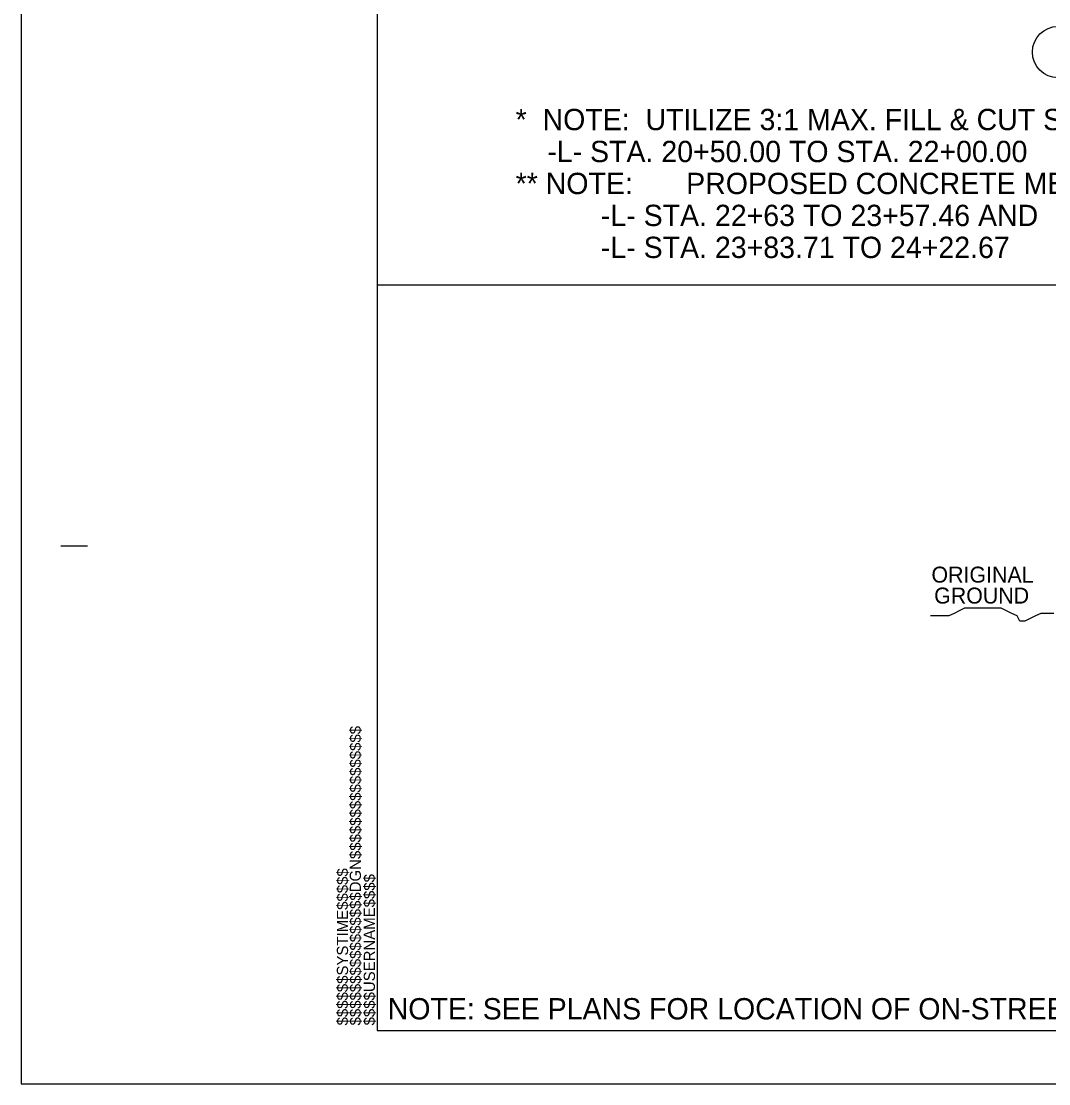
# Model space of a CAD drawing. Extents: x 1487909 to 1489267, y 497866 to 499814.
# Drawn here: x 1488883.26 to 1488931.46, y 498227.52 to 498277.38 of the extents above; entities that cross this region are included whole.
import ezdxf

# ---------------------------------------------------------------- set-up
doc = ezdxf.new("R2010")
doc.units = 0
for name, color, linetype in [('Scratch_Level_1', 7, 'Continuous'), ('Sheet Plot Border Outside CELL', 7, 'Continuous'), ('Sheet Typical CELL', 7, 'Continuous'), ('Typical Hinge Slope Arterial CELL', 7, 'Continuous'), ('Typical ID Circle CELL', 7, 'Continuous')]:
    doc.layers.add(name, color=color, linetype=linetype)

msp = doc.modelspace()

# ---------------------------------------------------------------- linework, layer by layer
at = {"layer": 'Scratch_Level_1'}
msp.add_line((1488899.964, 498265.02), (1489049.964, 498265.02), dxfattribs=at)
at = {"layer": 'Sheet Plot Border Outside CELL'}
msp.add_lwpolyline([(1489051.664, 498337.52), (1488883.264, 498337.52), (1488883.264, 498227.52), (1489051.664, 498227.52)], close=True, dxfattribs=at)
at = {"layer": 'Sheet Typical CELL'}
for p, q in [((1488885.114, 498252.77), (1488886.364, 498252.77)), ((1488899.964, 498230.02), (1488899.964, 498230.02)), ((1488899.964, 498230.02), (1488899.964, 498230.02)), ((1488899.964, 498230.02), (1488899.964, 498230.02)), ((1488899.964, 498230.02), (1488899.964, 498230.02)), ((1488899.964, 498230.02), (1488899.964, 498230.02)), ((1488899.964, 498230.02), (1488899.964, 498230.02))]:
    msp.add_line(p, q, dxfattribs=at)
msp.add_lwpolyline([(1489049.964, 498335.02), (1488899.964, 498335.02), (1488899.964, 498230.02), (1489049.964, 498230.02)], close=True, dxfattribs=at)
at = {"layer": 'Typical Hinge Slope Arterial CELL'}
msp.add_lwpolyline([(1488931.703, 498249.596), (1488931.333, 498249.596), (1488931.086, 498249.596), (1488930.84, 498249.474), (1488930.594, 498249.35), (1488930.347, 498249.226), (1488930.101, 498249.226), (1488929.977, 498249.474), (1488929.731, 498249.596), (1488929.485, 498249.72), (1488929.238, 498249.843), (1488928.992, 498249.843), (1488928.745, 498249.843), (1488928.499, 498249.843), (1488928.253, 498249.843), (1488928.006, 498249.843), (1488927.76, 498249.843), (1488927.514, 498249.843), (1488927.267, 498249.72), (1488927.021, 498249.596), (1488926.775, 498249.474), (1488926.405, 498249.474), (1488926.158, 498249.474), (1488925.912, 498249.474)], dxfattribs=at)
at = {"layer": 'Typical ID Circle CELL'}
msp.add_circle((1488931.903, 498275.935), 1.208, dxfattribs=at)

# ---------------------------------------------------------------- texts
at = {"layer": 'Sheet Typical CELL'}
for s, p in [('$$$$$$$$$$$$$$$$DGN$$$$$$$$$$$$$$$$', (1488899.199, 498230.256)), ('$$$$$$SYSTIME$$$$$', (1488898.594, 498230.256)), ('$$$$USERNAME$$$$', (1488899.856, 498230.257))]:
    msp.add_text(s, height=0.525, rotation=90, dxfattribs=at).set_placement(p)
at = {"layer": 'Typical Hinge Slope Arterial CELL'}
for s, height, p in [('*  NOTE:  UTILIZE 3:1 MAX. FILL & CUT SLOPES FROM', 1, (1488906.455, 498272.271)), ('    -L- STA. 20+50.00 TO STA. 22+00.00', 1, (1488906.455, 498270.771)), ('** NOTE:', 1, (1488906.455, 498269.271)), ('PROPOSED CONCRETE MEDIAN FROM', 1, (1488914.455, 498269.271)), ('-L- STA. 22+63 TO 23+57.46 AND', 1, (1488910.455, 498267.771)), ('-L- STA. 23+83.71 TO 24+22.67', 1, (1488910.455, 498266.271)), ('ORIGINAL', 0.75, (1488925.961, 498251.038)), ('GROUND', 0.75, (1488926.087, 498250.055)), ('NOTE: SEE PLANS FOR LOCATION OF ON-STREET PARKING', 1, (1488900.454, 498230.539))]:
    msp.add_text(s, height=height, dxfattribs=at).set_placement(p)

doc.saveas('drawing.dxf')
